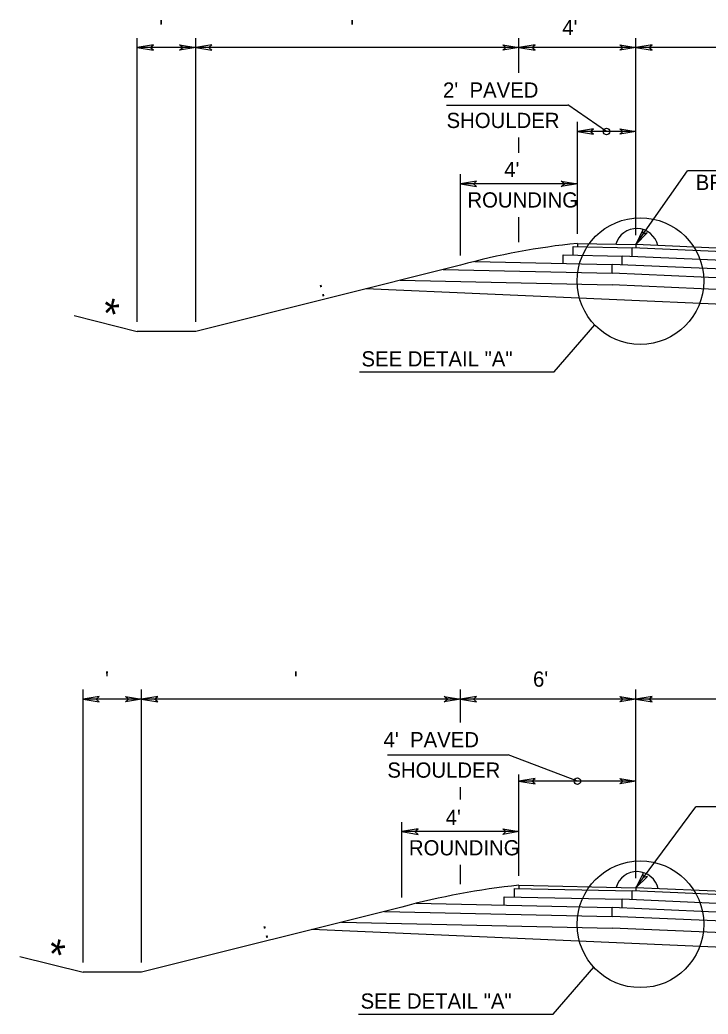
# Model space of a CAD drawing. Extents: x -592 to 1199, y -590 to 416.
# Drawn here: x 1001 to 1064.4, y -200.2 to -108.7 of the extents above; entities that cross this region are included whole.
import ezdxf

# ---------------------------------------------------------------- set-up
doc = ezdxf.new("R2010")
doc.units = 0
doc.layers.add('1', color=7, linetype='Continuous')
doc.layers.add('Des_ Drain_ Ftrs', color=7, linetype='Continuous')

msp = doc.modelspace()

# ---------------------------------------------------------------- linework, layer by layer
at = {"layer": '1'}
for p, q in [((1011.842, -136.465), (1011.842, -110.324)), ((1017.23, -136.465), (1017.23, -110.324)), ((1047.002, -113.534), (1047.002, -110.324)), ((1057.778, -128.476), (1057.778, -110.324)), ((1017.23, -111.204), (1011.842, -111.204)), ((1047.002, -111.204), (1017.23, -111.204)), ((1057.778, -111.204), (1047.002, -111.204)), ((1090.108, -111.204), (1057.778, -111.204)), ((1040.342, -116.514), (1051.483, -116.514)), ((1055.084, -118.939), (1051.498, -116.493)), ((1052.39, -128.359), (1052.39, -118.059)), ((1057.778, -118.939), (1052.39, -118.939)), ((1047.002, -120.888), (1047.002, -119.503)), ((1057.772, -129.356), (1062.551, -122.56)), ((1076.499, -122.56), (1062.551, -122.56)), ((1041.614, -130.369), (1041.614, -122.873)), ((1052.39, -123.753), (1041.613, -123.753)), ((1047.002, -129.137), (1047.002, -126.813)), ((1052.012, -130.312), (1052.012, -129.523)), ((1052.012, -129.531), (1057.432, -129.641)), ((1052.39, -129.239), (1057.772, -129.356)), ((1052.39, -129.239), (1052.39, -129.539)), ((1090.108, -131.068), (1057.432, -129.641)), ((1057.432, -130.451), (1057.432, -129.641)), ((1090.108, -130.768), (1057.772, -129.356)), ((1057.772, -129.356), (1057.772, -129.656)), ((1042.937, -130.903), (1055.587, -131.179)), ((1051.087, -130.292), (1056.51, -130.41)), ((1051.087, -131.081), (1051.087, -130.292)), ((1090.108, -131.877), (1056.51, -130.41)), ((1056.51, -131.22), (1056.51, -130.41)), ((1041.613, -131.249), (1017.23, -137.345)), ((1040.017, -131.648), (1055.587, -131.988)), ((1090.108, -132.686), (1055.587, -131.179)), ((1055.587, -131.988), (1055.587, -131.179)), ((1036.051, -132.64), (1055.587, -133.067)), ((1090.108, -133.496), (1055.587, -131.988)), ((1090.108, -135.922), (1032.913, -133.425)), ((1090.108, -134.574), (1055.587, -133.067)), ((1006.015, -135.888), (1011.842, -137.345)), ((1017.23, -137.345), (1011.842, -137.345)), ((1050.249, -141.079), (1053.989, -136.759)), ((1032.317, -141.079), (1050.249, -141.079)), ((1006.856, -195.499), (1006.856, -170.351)), ((1012.244, -195.499), (1012.244, -170.351)), ((1041.614, -173.391), (1041.614, -170.351)), ((1057.778, -187.728), (1057.778, -170.351)), ((1012.244, -171.231), (1006.856, -171.231)), ((1041.614, -171.231), (1012.244, -171.231)), ((1057.778, -171.231), (1041.614, -171.231)), ((1090.108, -171.231), (1057.778, -171.231)), ((1034.888, -176.362), (1046.029, -176.362)), ((1052.39, -178.787), (1046.029, -176.362)), ((1047.002, -187.493), (1047.002, -178.16)), ((1041.614, -180.478), (1041.614, -179.327)), ((1057.778, -178.787), (1047.002, -178.787)), ((1057.772, -188.608), (1063.313, -181.145)), ((1076.788, -181.145), (1063.313, -181.145)), ((1036.225, -189.504), (1036.225, -182.555)), ((1047.002, -183.435), (1036.225, -183.435)), ((1041.614, -188.27), (1041.614, -186.498)), ((1046.585, -189.445), (1046.585, -188.656)), ((1046.585, -188.664), (1057.432, -188.893)), ((1047.002, -188.373), (1057.772, -188.608)), ((1047.002, -188.373), (1047.002, -188.673)), ((1090.108, -190.019), (1057.772, -188.608)), ((1057.772, -188.608), (1057.772, -188.908)), ((1045.66, -189.425), (1056.51, -189.662)), ((1045.66, -190.214), (1045.66, -189.425)), ((1090.108, -190.32), (1057.432, -188.893)), ((1057.432, -189.702), (1057.432, -188.893)), ((1036.226, -190.383), (1012.244, -196.379)), ((1037.55, -190.037), (1055.587, -190.431)), ((1090.108, -191.938), (1055.587, -190.431)), ((1055.587, -191.241), (1055.587, -190.431)), ((1090.108, -191.129), (1056.51, -189.662)), ((1056.51, -190.471), (1056.51, -189.662)), ((1034.629, -190.783), (1055.603, -191.241)), ((1090.108, -192.747), (1055.603, -191.241)), ((1030.663, -191.774), (1055.587, -192.318)), ((1090.108, -193.826), (1055.587, -192.318)), ((1090.108, -195.174), (1027.926, -192.458)), ((1001.028, -194.922), (1006.856, -196.379)), ((1050.166, -200.242), (1053.906, -195.923)), ((1012.244, -196.379), (1006.856, -196.379)), ((1032.234, -200.242), (1050.166, -200.242))]:
    msp.add_line(p, q, dxfattribs=at)
for centre, radius in [((1055.084, -118.939), 0.3), ((1058.199, -132.715), 5.838), ((1052.39, -178.787), 0.3), ((1058.199, -191.967), 5.838)]:
    msp.add_circle(centre, radius, dxfattribs=at)
for centre, radius, start, end in [((1057.849, -129.87), 1.995, 12.28521, 163.87077), ((1059.285, -196.074), 67.19, 95.89012, 105.24869), ((1057.879, -189.111), 1.994, 11.96264, 164.1977), ((1053.898, -255.206), 67.188, 95.89109, 105.24966)]:
    msp.add_arc(centre, radius, start, end, dxfattribs=at)
at = {"layer": 'Des_ Drain_ Ftrs'}
for points in [[(1011.842, -111.204), (1013.331, -111.452), (1013.036, -111.204), (1013.331, -110.956)], [(1017.23, -111.204), (1015.742, -111.452), (1016.037, -111.204), (1015.742, -110.956)], [(1017.23, -111.204), (1018.719, -111.452), (1018.424, -111.204), (1018.719, -110.956)], [(1047.002, -111.204), (1045.513, -111.452), (1045.808, -111.204), (1045.513, -110.956)], [(1047.002, -111.204), (1048.49, -111.452), (1048.195, -111.204), (1048.49, -110.956)], [(1057.778, -111.204), (1056.29, -111.452), (1056.585, -111.204), (1056.29, -110.956)], [(1057.778, -111.204), (1059.267, -111.452), (1058.972, -111.204), (1059.267, -110.956)], [(1052.39, -118.939), (1053.878, -119.187), (1053.583, -118.939), (1053.878, -118.691)], [(1057.778, -118.939), (1056.29, -119.187), (1056.585, -118.939), (1056.29, -118.691)], [(1041.613, -123.753), (1043.102, -124.002), (1042.807, -123.753), (1043.102, -123.505)], [(1052.39, -123.753), (1050.902, -124.002), (1051.197, -123.753), (1050.902, -123.505)], [(1057.772, -129.356), (1058.831, -128.282), (1058.458, -128.38), (1058.425, -127.996)], [(1006.856, -171.231), (1008.344, -171.48), (1008.049, -171.231), (1008.344, -170.983)], [(1012.244, -171.231), (1010.755, -171.48), (1011.05, -171.231), (1010.755, -170.983)], [(1012.244, -171.231), (1013.732, -171.48), (1013.437, -171.231), (1013.732, -170.983)], [(1041.614, -171.231), (1040.125, -171.48), (1040.42, -171.231), (1040.125, -170.983)], [(1041.614, -171.231), (1043.102, -171.48), (1042.807, -171.231), (1043.102, -170.983)], [(1057.778, -171.231), (1056.29, -171.48), (1056.585, -171.231), (1056.29, -170.983)], [(1057.778, -171.231), (1059.267, -171.48), (1058.972, -171.231), (1059.267, -170.983)], [(1047.002, -178.787), (1048.49, -179.035), (1048.195, -178.787), (1048.49, -178.538)], [(1057.778, -178.787), (1056.29, -179.035), (1056.585, -178.787), (1056.29, -178.538)], [(1036.225, -183.435), (1037.714, -183.683), (1037.419, -183.435), (1037.714, -183.186)], [(1047.002, -183.435), (1045.513, -183.683), (1045.808, -183.435), (1045.513, -183.186)], [(1057.772, -188.608), (1058.859, -187.561), (1058.483, -187.65), (1058.46, -187.265)]]:
    msp.add_lwpolyline(points, close=True, dxfattribs=at)

# ---------------------------------------------------------------- texts
at = {"layer": '1'}
for s, p in [(" '", (1013.341, -110.053)), ("  '", (1030.42, -110.053)), ("4'", (1051, -110.053)), ("2'  PAVED", (1040.015, -115.814)), ('SHOULDER', (1040.34, -118.614)), ("4'", (1045.649, -123.138)), ('BREAKOVER', (1063.296, -124.326)), ('ROUNDING', (1042.26, -125.938)), ('SEE DETAIL "A"', (1032.502, -140.576)), (" '", (1008.354, -170.08)), ("  '", (1025.233, -170.08)), ("6'", (1048.305, -170.08)), ("4'  PAVED", (1034.537, -175.662)), ('SHOULDER', (1034.886, -178.462)), ("4'", (1040.261, -182.819)), ('ROUNDING', (1036.872, -185.619)), ('SEE DETAIL "A"', (1032.419, -199.739))]:
    msp.add_text(s, height=1.4, dxfattribs=at).set_placement(p)
for s, height, rotation, p in [(' : ', 1.4, 14.22821, (1028.242, -134.31)), ('*', 2.8, 347.15207, (1008.327, -136.913)), (' : ', 1.4, 14.22821, (1023.055, -193.394)), ('*', 2.8, 347.15207, (1003.341, -195.947))]:
    msp.add_text(s, height=height, rotation=rotation, dxfattribs=at).set_placement(p)

doc.saveas('drawing.dxf')
